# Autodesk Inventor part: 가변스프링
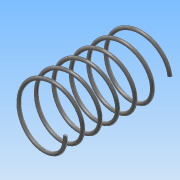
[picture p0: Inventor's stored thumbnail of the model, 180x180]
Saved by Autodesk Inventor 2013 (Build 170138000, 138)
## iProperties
Created: 2016-12
Part Number: 가변스프링
Material: 스테인리스강
Document SubType Name: Modeling
Designer: Administrator
Density: 8.08 g/cm^3
Mass: 1.90732 g
Surface Area: 9.48706 cm^2
Volume: 0.236055 cm^3
Author: Administrator
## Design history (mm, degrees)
sketch "스케치1"
  geometry: L1 (0, 0)-(8, 0); L2 (8, 0)-(8, 30.5); L3 (8, 30.5)-(0, 30.5); L4 (0, 30.5)-(0, 0); C1 r 0.5 at (8, 0)
  constraints: 8 end point, 2 parallel, 1 centre point, 1 coincident, 1 horizontal, 1 perpendicular
  dimensions: "d0" = 1 diameter of C1; "d1" = 16 diameter of L2 L4; "d2" = 30.49998 distance of L1.end L2.end (derived)
feature "코일1" sketch "스케치1" pitch "d3" = 10; turns "d5" = 6; dims "d4" = 30.49991 (computed from d2), "d6" = 0, angle "d7" = 90 deg, angle "d8" = 90 deg, "d9" = 0, "d10" = 0
sketch "스케치2"
  geometry: L1 (-15, 35)-(15, 35); L2 (15, 35)-(15, 0); L3 (15, 0)-(-15, 0); L4 (-15, 0)-(-15, 35); 2 further points
  constraints: 8 end point, 2 midpoint, 2 parallel, 1 coincident, 1 horizontal, 1 perpendicular
  dimensions: "d11" = 35 distance of L1.end L2.end (derived); "d13" = 30 distance of L1.start L1.end
extrude "돌출1" sketch "스케치2" stored distance "d14" = 50; taper "d15" = 0 deg
node "솔리드1"
